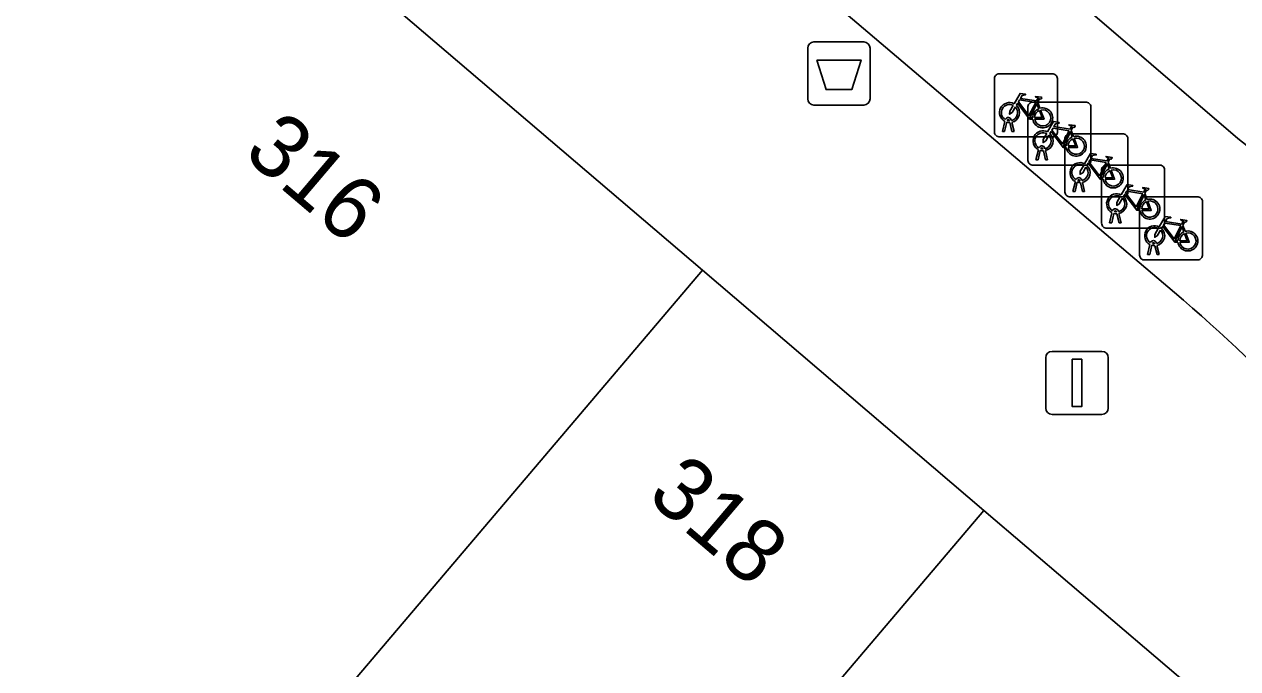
# Model space of a CAD drawing. Extents: x 162344 to 162869, y 381217 to 381818.
# Drawn here: x 162822.25 to 162841.5, y 381526.4 to 381536.62 of the extents above; entities that cross this region are included whole.
import ezdxf

# ---------------------------------------------------------------- set-up
doc = ezdxf.new("R2010")
doc.units = 0
for name, color, linetype in [('IMGEO_Afvalbak', 7, 'Continuous'), ('IMGEO_Berm_groen', 7, 'Continuous'), ('IMGEO_Fietsenrek', 7, 'Continuous'), ('IMGEO_Fietspad_gesloten', 7, 'Continuous'), ('IMGEO_Lichtmast', 7, 'Continuous'), ('IMGEO_Pand', 7, 'Continuous'), ('IMGEO_Pand_nummerreeks', 7, 'Continuous'), ('IMGEO_Voetpad_open', 7, 'Continuous')]:
    doc.layers.add(name, color=color, linetype=linetype)

msp = doc.modelspace()

# ---------------------------------------------------------------- linework, layer by layer
at = {"layer": 'IMGEO_Afvalbak'}
for p, q in [((162834.779, 381536.343), (162835.569, 381536.343)), ((162835.569, 381536.343), (162834.779, 381536.343)), ((162834.679, 381535.443), (162834.679, 381536.243)), ((162834.679, 381536.243), (162834.679, 381535.443)), ((162835.669, 381536.243), (162835.669, 381535.443)), ((162835.669, 381535.443), (162835.669, 381536.243)), ((162835.569, 381535.343), (162834.779, 381535.343)), ((162834.779, 381535.343), (162835.569, 381535.343))]:
    msp.add_line(p, q, dxfattribs=at)
msp.add_lwpolyline([(162834.822, 381536.057), (162835.526, 381536.057), (162835.377, 381535.587), (162834.971, 381535.587), (162834.822, 381536.057)], dxfattribs=at)
for centre, start, end in [((162834.779, 381536.243), 90, 180), ((162834.779, 381536.243), 90, 180), ((162835.569, 381536.243), 0, 90), ((162835.569, 381536.243), 360, 90), ((162834.779, 381535.443), 180, 270), ((162834.779, 381535.443), 180, 270), ((162835.569, 381535.443), 270, 0), ((162835.569, 381535.443), 270, 0)]:
    msp.add_arc(centre, 0.1, start, end, dxfattribs=at)
at = {"layer": 'IMGEO_Berm_groen'}
msp.add_lwpolyline([(162839.907, 381540.707), (162837.376, 381538.357), (162841.502, 381534.811)], dxfattribs=at)
msp.add_arc((162827.147, 381516.12), 23.567, 37.9331, 52.4744, dxfattribs=at)
at = {"layer": 'IMGEO_Fietsenrek'}
for p, q in [((162837.641, 381534.913), (162837.641, 381535.754)), ((162837.641, 381535.754), (162837.641, 381534.913)), ((162837.716, 381535.838), (162838.557, 381535.838)), ((162838.557, 381535.838), (162837.716, 381535.838)), ((162838.641, 381535.763), (162838.641, 381534.922)), ((162838.641, 381534.922), (162838.641, 381535.763)), ((162838.173, 381534.464), (162838.173, 381535.305)), ((162838.173, 381535.305), (162838.173, 381534.464)), ((162838.248, 381535.389), (162839.089, 381535.389)), ((162839.089, 381535.389), (162838.248, 381535.389)), ((162838.328, 381535.387), (162838.364, 381535.292)), ((162839.173, 381535.314), (162839.173, 381534.473)), ((162839.173, 381534.473), (162839.173, 381535.314)), ((162837.879, 381535.094), (162837.878, 381535.098)), ((162837.91, 381535.105), (162837.911, 381535.098)), ((162837.768, 381534.922), (162837.807, 381535.082)), ((162837.802, 381534.922), (162837.768, 381534.922)), ((162837.837, 381535.07), (162837.802, 381534.922)), ((162837.92, 381534.922), (162837.886, 381535.064)), ((162837.918, 381535.068), (162837.953, 381534.922)), ((162837.953, 381534.922), (162837.92, 381534.922)), ((162838.86, 381534.938), (162838.896, 381534.843)), ((162838.566, 381534.838), (162837.725, 381534.838)), ((162837.725, 381534.838), (162838.566, 381534.838)), ((162838.76, 381533.96), (162838.76, 381534.801)), ((162838.76, 381534.801), (162838.76, 381533.96)), ((162838.835, 381534.885), (162839.676, 381534.885)), ((162839.676, 381534.885), (162838.835, 381534.885)), ((162839.76, 381534.81), (162839.76, 381533.969)), ((162839.76, 381533.969), (162839.76, 381534.81)), ((162838.3, 381534.473), (162838.339, 381534.633)), ((162838.369, 381534.621), (162838.334, 381534.473)), ((162838.411, 381534.645), (162838.41, 381534.649)), ((162838.452, 381534.473), (162838.418, 381534.615)), ((162838.442, 381534.656), (162838.443, 381534.649)), ((162838.45, 381534.619), (162838.485, 381534.473)), ((162839.098, 381534.389), (162838.257, 381534.389)), ((162838.257, 381534.389), (162839.098, 381534.389)), ((162838.334, 381534.473), (162838.3, 381534.473)), ((162838.485, 381534.473), (162838.452, 381534.473)), ((162839.416, 381534.391), (162840.257, 381534.391)), ((162840.257, 381534.391), (162839.416, 381534.391)), ((162839.447, 381534.434), (162839.483, 381534.339)), ((162838.998, 381534.141), (162838.997, 381534.145)), ((162839.029, 381534.152), (162839.03, 381534.145)), ((162839.341, 381533.466), (162839.341, 381534.307)), ((162839.341, 381534.307), (162839.341, 381533.466)), ((162840.341, 381534.316), (162840.341, 381533.475)), ((162840.341, 381533.475), (162840.341, 381534.316)), ((162838.887, 381533.969), (162838.926, 381534.129)), ((162838.921, 381533.969), (162838.887, 381533.969)), ((162838.956, 381534.117), (162838.921, 381533.969)), ((162839.039, 381533.969), (162839.005, 381534.111)), ((162839.037, 381534.115), (162839.072, 381533.969)), ((162839.072, 381533.969), (162839.039, 381533.969)), ((162839.685, 381533.885), (162838.844, 381533.885)), ((162838.844, 381533.885), (162839.685, 381533.885)), ((162839.944, 381532.96), (162839.944, 381533.801)), ((162839.944, 381533.801), (162839.944, 381532.96)), ((162840.019, 381533.885), (162840.86, 381533.885)), ((162840.86, 381533.885), (162840.019, 381533.885)), ((162840.028, 381533.94), (162840.064, 381533.845)), ((162840.944, 381533.81), (162840.944, 381532.969)), ((162840.944, 381532.969), (162840.944, 381533.81)), ((162839.468, 381533.475), (162839.507, 381533.635)), ((162839.537, 381533.623), (162839.502, 381533.475)), ((162839.579, 381533.647), (162839.578, 381533.651)), ((162839.62, 381533.475), (162839.586, 381533.617)), ((162839.61, 381533.658), (162839.611, 381533.651)), ((162839.618, 381533.621), (162839.653, 381533.475)), ((162840.266, 381533.391), (162839.425, 381533.391)), ((162839.425, 381533.391), (162840.266, 381533.391)), ((162839.502, 381533.475), (162839.468, 381533.475)), ((162839.653, 381533.475), (162839.62, 381533.475)), ((162840.631, 381533.434), (162840.667, 381533.339)), ((162840.071, 381532.969), (162840.11, 381533.129)), ((162840.14, 381533.117), (162840.105, 381532.969)), ((162840.182, 381533.141), (162840.181, 381533.145)), ((162840.223, 381532.969), (162840.189, 381533.111)), ((162840.213, 381533.152), (162840.214, 381533.145)), ((162840.221, 381533.115), (162840.256, 381532.969)), ((162840.869, 381532.885), (162840.028, 381532.885)), ((162840.028, 381532.885), (162840.869, 381532.885)), ((162840.105, 381532.969), (162840.071, 381532.969)), ((162840.256, 381532.969), (162840.223, 381532.969))]:
    msp.add_line(p, q, dxfattribs=at)
for points in [[(162837.954, 381535.364), (162838.049, 381535.528), (162838.135, 381535.514), (162838.137, 381535.505), (162838.081, 381535.494), (162838.054, 381535.449), (162838.31, 381535.408)], [(162837.975, 381535.312), (162837.923, 381535.222), (162837.883, 381535.197), (162837.884, 381535.244), (162837.939, 381535.338)], [(162838.25, 381535.12), (162838.2, 381535.12), (162838.009, 381535.371), (162837.99, 381535.339)], [(162838.297, 381535.383), (162838.04, 381535.424), (162838.023, 381535.395), (162838.19, 381535.175), (162838.297, 381535.383)], [(162838.345, 381535.285), (162838.315, 381535.362), (162838.206, 381535.144), (162838.249, 381535.144)], [(162838.31, 381535.408), (162838.335, 381535.457), (162838.329, 381535.461), (162838.306, 381535.465), (162838.294, 381535.472), (162838.293, 381535.475), (162838.295, 381535.48), (162838.39, 381535.465), (162838.392, 381535.455), (162838.382, 381535.442), (162838.37, 381535.436), (162838.356, 381535.442), (162838.328, 381535.387)], [(162838.279, 381535.144), (162838.399, 381535.143), (162838.355, 381535.257)], [(162838.375, 381535.264), (162838.43, 381535.119), (162838.28, 381535.119)], [(162838.486, 381534.915), (162838.581, 381535.079), (162838.667, 381535.065), (162838.669, 381535.056), (162838.613, 381535.045), (162838.586, 381535), (162838.842, 381534.959)], [(162838.782, 381534.671), (162838.732, 381534.671), (162838.541, 381534.922), (162838.522, 381534.89)], [(162838.829, 381534.934), (162838.572, 381534.975), (162838.555, 381534.946), (162838.722, 381534.726), (162838.829, 381534.934)], [(162838.877, 381534.836), (162838.847, 381534.913), (162838.738, 381534.695), (162838.781, 381534.695)], [(162838.842, 381534.959), (162838.867, 381535.008), (162838.861, 381535.012), (162838.838, 381535.016), (162838.826, 381535.023), (162838.825, 381535.026), (162838.827, 381535.031), (162838.922, 381535.016), (162838.924, 381535.006), (162838.914, 381534.993), (162838.902, 381534.987), (162838.888, 381534.993), (162838.86, 381534.938)], [(162838.507, 381534.863), (162838.455, 381534.773), (162838.415, 381534.748), (162838.416, 381534.795), (162838.471, 381534.889)], [(162838.811, 381534.695), (162838.931, 381534.694), (162838.887, 381534.808)], [(162838.907, 381534.815), (162838.962, 381534.67), (162838.812, 381534.67)], [(162839.073, 381534.411), (162839.168, 381534.575), (162839.254, 381534.561), (162839.256, 381534.552), (162839.2, 381534.541), (162839.173, 381534.496), (162839.429, 381534.455)], [(162839.429, 381534.455), (162839.454, 381534.504), (162839.448, 381534.508), (162839.425, 381534.512), (162839.413, 381534.519), (162839.412, 381534.522), (162839.414, 381534.527), (162839.509, 381534.512), (162839.511, 381534.502), (162839.501, 381534.489), (162839.489, 381534.483), (162839.475, 381534.489), (162839.447, 381534.434)], [(162839.094, 381534.359), (162839.042, 381534.269), (162839.002, 381534.244), (162839.003, 381534.291), (162839.058, 381534.385)], [(162839.369, 381534.167), (162839.319, 381534.167), (162839.128, 381534.418), (162839.109, 381534.386)], [(162839.416, 381534.43), (162839.159, 381534.471), (162839.142, 381534.442), (162839.309, 381534.222), (162839.416, 381534.43)], [(162839.464, 381534.332), (162839.434, 381534.409), (162839.325, 381534.191), (162839.368, 381534.191)], [(162839.398, 381534.191), (162839.518, 381534.19), (162839.474, 381534.304)], [(162839.494, 381534.311), (162839.549, 381534.166), (162839.399, 381534.166)], [(162839.654, 381533.917), (162839.749, 381534.081), (162839.835, 381534.067), (162839.837, 381534.058), (162839.781, 381534.047), (162839.754, 381534.002), (162840.01, 381533.961)], [(162839.997, 381533.936), (162839.74, 381533.977), (162839.723, 381533.948), (162839.89, 381533.728), (162839.997, 381533.936)], [(162840.01, 381533.961), (162840.035, 381534.01), (162840.029, 381534.014), (162840.006, 381534.018), (162839.994, 381534.025), (162839.993, 381534.028), (162839.995, 381534.033), (162840.09, 381534.018), (162840.092, 381534.008), (162840.082, 381533.995), (162840.07, 381533.989), (162840.056, 381533.995), (162840.028, 381533.94)], [(162839.675, 381533.865), (162839.623, 381533.775), (162839.583, 381533.75), (162839.584, 381533.797), (162839.639, 381533.891)], [(162839.95, 381533.673), (162839.9, 381533.673), (162839.709, 381533.924), (162839.69, 381533.892)], [(162840.045, 381533.838), (162840.015, 381533.915), (162839.906, 381533.697), (162839.949, 381533.697)], [(162839.979, 381533.697), (162840.099, 381533.696), (162840.055, 381533.81)], [(162840.075, 381533.817), (162840.13, 381533.672), (162839.98, 381533.672)], [(162840.257, 381533.411), (162840.352, 381533.575), (162840.438, 381533.561), (162840.44, 381533.552), (162840.384, 381533.541), (162840.357, 381533.496), (162840.613, 381533.455)], [(162840.278, 381533.359), (162840.226, 381533.269), (162840.186, 381533.244), (162840.187, 381533.291), (162840.242, 381533.385)], [(162840.553, 381533.167), (162840.503, 381533.167), (162840.312, 381533.418), (162840.293, 381533.386)], [(162840.6, 381533.43), (162840.343, 381533.471), (162840.326, 381533.442), (162840.493, 381533.222), (162840.6, 381533.43)], [(162840.648, 381533.332), (162840.618, 381533.409), (162840.509, 381533.191), (162840.552, 381533.191)], [(162840.613, 381533.455), (162840.638, 381533.504), (162840.632, 381533.508), (162840.609, 381533.512), (162840.597, 381533.519), (162840.596, 381533.522), (162840.598, 381533.527), (162840.693, 381533.512), (162840.695, 381533.502), (162840.685, 381533.489), (162840.673, 381533.483), (162840.659, 381533.489), (162840.631, 381533.434)], [(162840.582, 381533.191), (162840.702, 381533.19), (162840.658, 381533.304)], [(162840.678, 381533.311), (162840.733, 381533.166), (162840.583, 381533.166)]]:
    msp.add_lwpolyline(points, dxfattribs=at)
for centre, radius, start, end in [((162837.719, 381535.76), 0.0779, 92.4484, 184.2845), ((162837.719, 381535.76), 0.0779, 92.4484, 184.2845), ((162838.563, 381535.76), 0.0779, 2.4484, 94.2845), ((162838.563, 381535.76), 0.0779, 2.4484, 94.2845), ((162837.881, 381535.223), 0.159, 62.6766, 242.1369), ((162837.881, 381535.223), 0.129, 63.3192, 238.903), ((162837.881, 381535.223), 0.129, 283.6043, 43.4302), ((162837.881, 381535.223), 0.159, 283.5766, 46.6042), ((162838.251, 381535.311), 0.0779, 92.4484, 184.2845), ((162838.251, 381535.311), 0.0779, 92.4484, 184.2845), ((162838.408, 381535.139), 0.159, 187.0065, 105.7708), ((162839.095, 381535.311), 0.0779, 2.4484, 94.2845), ((162839.095, 381535.311), 0.0779, 2.4484, 94.2845), ((162837.861, 381535.094), 0.0499, 12.8025, 158.6934), ((162837.861, 381535.094), 0.0174, 12.8025, 163.4502), ((162837.881, 381535.223), 0.129, 253.415, 269.0204), ((162838.408, 381535.139), 0.159, 113.3408, 178.3217), ((162838.408, 381535.139), 0.129, 113.923, 177.9556), ((162838.408, 381535.139), 0.129, 188.6715, 104.5883), ((162837.719, 381534.916), 0.0779, 182.4484, 274.2845), ((162837.719, 381534.916), 0.0779, 182.4484, 274.2845), ((162837.881, 381535.223), 0.159, 253.9967, 271.7867), ((162838.413, 381534.774), 0.159, 62.6766, 242.1369), ((162838.563, 381534.916), 0.0779, 272.4484, 4.2845), ((162838.563, 381534.916), 0.0779, 272.4484, 4.2845), ((162838.413, 381534.774), 0.129, 63.3192, 238.903), ((162838.413, 381534.774), 0.129, 283.6043, 43.4302), ((162838.413, 381534.774), 0.159, 283.5766, 46.6042), ((162838.838, 381534.807), 0.0779, 92.4484, 184.2845), ((162838.838, 381534.807), 0.0779, 92.4484, 184.2845), ((162838.94, 381534.69), 0.159, 113.3408, 178.3217), ((162838.94, 381534.69), 0.159, 187.0065, 105.7708), ((162838.94, 381534.69), 0.129, 113.923, 177.9556), ((162838.94, 381534.69), 0.129, 188.6715, 104.5883), ((162839.682, 381534.807), 0.0779, 2.4484, 94.2845), ((162839.682, 381534.807), 0.0779, 2.4484, 94.2845), ((162838.393, 381534.645), 0.0499, 12.8025, 158.6934), ((162838.413, 381534.774), 0.159, 253.9967, 271.7867), ((162838.393, 381534.645), 0.0174, 12.8025, 163.4502), ((162838.413, 381534.774), 0.129, 253.415, 269.0204), ((162838.251, 381534.467), 0.0779, 182.4484, 274.2845), ((162838.251, 381534.467), 0.0779, 182.4484, 274.2845), ((162839, 381534.27), 0.159, 62.6766, 242.1369), ((162839, 381534.27), 0.129, 63.3192, 238.903), ((162839, 381534.27), 0.129, 283.6043, 43.4302), ((162839, 381534.27), 0.159, 283.5766, 46.6042), ((162839.095, 381534.467), 0.0779, 272.4484, 4.2845), ((162839.095, 381534.467), 0.0779, 272.4484, 4.2845), ((162839.419, 381534.313), 0.0779, 92.4484, 184.2845), ((162839.419, 381534.313), 0.0779, 92.4484, 184.2845), ((162839.527, 381534.186), 0.159, 113.3408, 178.3217), ((162839.527, 381534.186), 0.159, 187.0065, 105.7708), ((162840.263, 381534.313), 0.0779, 2.4484, 94.2845), ((162840.263, 381534.313), 0.0779, 2.4484, 94.2845), ((162838.98, 381534.141), 0.0499, 12.8025, 158.6934), ((162838.98, 381534.141), 0.0174, 12.8025, 163.4502), ((162839, 381534.27), 0.129, 253.415, 269.0204), ((162839.527, 381534.186), 0.129, 113.923, 177.9556), ((162839.527, 381534.186), 0.129, 188.6715, 104.5883), ((162838.838, 381533.963), 0.0779, 182.4484, 274.2845), ((162838.838, 381533.963), 0.0779, 182.4484, 274.2845), ((162839, 381534.27), 0.159, 253.9967, 271.7867), ((162839.682, 381533.963), 0.0779, 272.4484, 4.2845), ((162839.682, 381533.963), 0.0779, 272.4484, 4.2845), ((162839.581, 381533.776), 0.159, 62.6766, 242.1369), ((162839.581, 381533.776), 0.129, 63.3192, 238.903), ((162839.581, 381533.776), 0.129, 283.6043, 43.4302), ((162839.581, 381533.776), 0.159, 283.5766, 46.6042), ((162840.022, 381533.807), 0.0779, 92.4484, 184.2845), ((162840.022, 381533.807), 0.0779, 92.4484, 184.2845), ((162840.108, 381533.692), 0.159, 113.3408, 178.3217), ((162840.108, 381533.692), 0.159, 187.0065, 105.7708), ((162840.108, 381533.692), 0.129, 113.923, 177.9556), ((162840.108, 381533.692), 0.129, 188.6715, 104.5883), ((162840.866, 381533.807), 0.0779, 2.4484, 94.2845), ((162840.866, 381533.807), 0.0779, 2.4484, 94.2845), ((162839.561, 381533.647), 0.0499, 12.8025, 158.6934), ((162839.581, 381533.776), 0.159, 253.9967, 271.7867), ((162839.561, 381533.647), 0.0174, 12.8025, 163.4502), ((162839.581, 381533.776), 0.129, 253.415, 269.0204), ((162839.419, 381533.469), 0.0779, 182.4484, 274.2845), ((162839.419, 381533.469), 0.0779, 182.4484, 274.2845), ((162840.184, 381533.27), 0.159, 62.6766, 242.1369), ((162840.184, 381533.27), 0.129, 63.3192, 238.903), ((162840.184, 381533.27), 0.159, 283.5766, 46.6042), ((162840.263, 381533.469), 0.0779, 272.4484, 4.2845), ((162840.263, 381533.469), 0.0779, 272.4484, 4.2845), ((162840.164, 381533.141), 0.0499, 12.8025, 158.6934), ((162840.184, 381533.27), 0.129, 283.6043, 43.4302), ((162840.711, 381533.186), 0.159, 113.3408, 178.3217), ((162840.711, 381533.186), 0.159, 187.0065, 105.7708), ((162840.711, 381533.186), 0.129, 113.923, 177.9556), ((162840.711, 381533.186), 0.129, 188.6715, 104.5883), ((162840.184, 381533.27), 0.159, 253.9967, 271.7867), ((162840.164, 381533.141), 0.0174, 12.8025, 163.4502), ((162840.184, 381533.27), 0.129, 253.415, 269.0204), ((162840.022, 381532.963), 0.0779, 182.4484, 274.2845), ((162840.022, 381532.963), 0.0779, 182.4484, 274.2845), ((162840.866, 381532.963), 0.0779, 272.4484, 4.2845), ((162840.866, 381532.963), 0.0779, 272.4484, 4.2845)]:
    msp.add_arc(centre, radius, start, end, dxfattribs=at)
at = {"layer": 'IMGEO_Fietspad_gesloten'}
for points in [[(162684.232, 381664.825), (162688.355, 381661.085), (162692.352, 381657.601), (162694.144, 381656.087), (162695.755, 381654.725), (162704.011, 381647.75), (162705.608, 381646.401), (162718.443, 381635.556), (162720.034, 381634.212), (162732.624, 381623.574), (162734.239, 381622.209), (162743.076, 381614.743), (162746.831, 381611.57), (162748.438, 381610.212), (162761.023, 381599.578), (162762.605, 381598.241), (162775.215, 381587.585), (162776.8, 381586.246), (162789.414, 381575.587), (162791.002, 381574.245), (162797.286, 381568.935), (162800.436, 381566.273), (162829.055, 381542.09), (162840.499, 381532.368)], [(162841.502, 381534.811), (162837.376, 381538.357), (162836.448, 381539.154), (162830.443, 381544.315), (162820.68, 381552.549), (162817.483, 381555.246), (162799.811, 381570.151), (162796.513, 381572.933), (162782.289, 381584.929), (162779.07, 381587.644), (162768.998, 381596.139), (162763.006, 381601.204), (162759.809, 381603.905), (162743.753, 381617.476), (162740.536, 381620.194), (162722.898, 381635.101), (162719.685, 381637.816), (162708.354, 381647.393), (162705.095, 381650.146), (162702.028, 381652.737), (162694.013, 381659.509), (162690.775, 381662.288)]]:
    msp.add_lwpolyline(points, dxfattribs=at)
for centre, radius, start, end in [((162827.147, 381516.12), 23.567, 37.9331, 52.4744), ((162823.312, 381512.134), 26.548, 36.6305, 49.6552)]:
    msp.add_arc(centre, radius, start, end, dxfattribs=at)
at = {"layer": 'IMGEO_Lichtmast'}
for p, q in [((162838.457, 381530.534), (162838.457, 381531.334)), ((162838.457, 381531.334), (162838.457, 381530.534)), ((162838.557, 381531.434), (162839.347, 381531.434)), ((162839.347, 381531.434), (162838.557, 381531.434)), ((162839.447, 381531.334), (162839.447, 381530.534)), ((162839.447, 381530.534), (162839.447, 381531.334)), ((162839.347, 381530.434), (162838.557, 381530.434)), ((162838.557, 381530.434), (162839.347, 381530.434))]:
    msp.add_line(p, q, dxfattribs=at)
msp.add_lwpolyline([(162838.877, 381531.309), (162839.027, 381531.309), (162839.027, 381530.559), (162838.877, 381530.559), (162838.877, 381531.309)], dxfattribs=at)
for centre, start, end in [((162838.557, 381531.334), 90, 180), ((162838.557, 381531.334), 90, 180), ((162839.347, 381531.334), 0, 90), ((162839.347, 381531.334), 360, 90), ((162838.557, 381530.534), 180, 270), ((162838.557, 381530.534), 180, 270), ((162839.347, 381530.534), 270, 0), ((162839.347, 381530.534), 270, 0)]:
    msp.add_arc(centre, 0.1, start, end, dxfattribs=at)
at = {"layer": 'IMGEO_Pand'}
for points in [[(162833.01, 381532.723), (162824.698, 381539.819), (162811.823, 381524.665), (162813.346, 381523.389), (162814.567, 381524.826), (162818.623, 381521.38), (162821.151, 381518.767)], [(162837.476, 381528.911), (162833.01, 381532.723), (162821.151, 381518.767), (162825.134, 381514.651), (162830.872, 381521.405), (162831.004, 381521.293)], [(162837.476, 381528.911), (162831.004, 381521.293), (162830.872, 381521.405), (162825.134, 381514.651), (162829.673, 381509.959), (162832.103, 381507.448), (162844.977, 381522.508)]]:
    msp.add_lwpolyline(points, close=True, dxfattribs=at)
at = {"layer": 'IMGEO_Voetpad_open'}
for points in [[(162840.499, 381532.368), (162829.055, 381542.09), (162800.436, 381566.273)], [(162800.041, 381565.929), (162797.896, 381563.425), (162797.494, 381562.956), (162797.667, 381562.809), (162802.659, 381558.563), (162807.896, 381554.107), (162813.298, 381549.512), (162818.905, 381544.742), (162820.872, 381543.085), (162824.698, 381539.819), (162833.01, 381532.723), (162837.476, 381528.911), (162844.977, 381522.508), (162847.475, 381523.854), (162844.617, 381527.974)]]:
    msp.add_lwpolyline(points, dxfattribs=at)
msp.add_arc((162823.312, 381512.134), 26.548, 36.6305, 49.6552, dxfattribs=at)

# ---------------------------------------------------------------- texts
at = {"layer": 'IMGEO_Pand_nummerreeks'}
for s, rotation, p in [('316', 319.6466, (162825.7, 381534.546)), ('318', 319.658, (162832.105, 381529.105))]:
    msp.add_text(s, height=1, rotation=rotation, dxfattribs=at).set_placement(p)

doc.saveas('drawing.dxf')
